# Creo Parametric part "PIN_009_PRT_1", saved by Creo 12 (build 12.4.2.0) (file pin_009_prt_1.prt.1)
Units: Custom; MM, KILOGRAM, SECS

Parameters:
  PTC_WM_ITERATION = "0"
  PTC_WM_VERSION = "-.0"
  PTC_WM_LIFECYCLE_STATE = "In Work"
  PTC_WM_LIFECYCLE = "MO_CADDocument"
  PTC_WM_CREATED_BY = "Maximilian Roepper (Z0017RMS: MO)"
  PTC_WM_CREATED_ON = "18-Sep-26 11:36:42 AM"
  PTC_WM_MODIFIED_BY = "Maximilian Roepper (Z0017RMS: MO)"
  PTC_WM_MODIFIED_ON = "18-Sep-26 11:36:46 AM"
  PDMLINKNUMBER = "PDM000071454929"
  PTC_WM_NAME = "pin_009_prt_1.prt"
  PTC_WM_NUMBER = "PDM000071454929"

Other parameters: WEIGHT, WEIGHT_FACTOR, WEIGHT_ADD, _MASS_TEMP, _DIFF_TEMP, MC_ERRORS, SUPPLIER

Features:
  1. coordinate system
  2. datum plane "PRT_YZ"
  3. datum plane "PRT_XY"
  4. datum plane "PRT_XZ"
  5. coordinate system
  6. datum axis
  7. datum axis
  8. datum axis
  9. coordinate system
  10. imported feature
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
Other named items: PRT, SIEMENS_MO, DRW_VIEW_ORG, PRT_X, PRT_Y, PRT_Z, CS0, ROUGH_GROB

Layers: 00_STD_CSYS-KSYS, 01_STD_PLANES-EBENEN, 02_STD_AXES-ACHSEN, 03_STD_CSYS-KSYS, 24_IMPORT_FEAT-IMPORT_KE

Surfaces: 9 plane, 1 cylinder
